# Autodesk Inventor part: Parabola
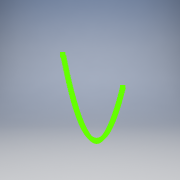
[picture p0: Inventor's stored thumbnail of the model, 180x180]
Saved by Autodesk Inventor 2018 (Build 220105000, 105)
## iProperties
Created: 2008-02
Part Number: Parabola
Document SubType Name: Modeling
Designer: Autodesk, Inc.
Density: 1 g/cm^3
Material: Generic
Appearance: Default
Author: Autodesk, Inc.
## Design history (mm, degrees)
sketch "Sketch1"
  geometry: 300 further points
  constraints: 300 other
